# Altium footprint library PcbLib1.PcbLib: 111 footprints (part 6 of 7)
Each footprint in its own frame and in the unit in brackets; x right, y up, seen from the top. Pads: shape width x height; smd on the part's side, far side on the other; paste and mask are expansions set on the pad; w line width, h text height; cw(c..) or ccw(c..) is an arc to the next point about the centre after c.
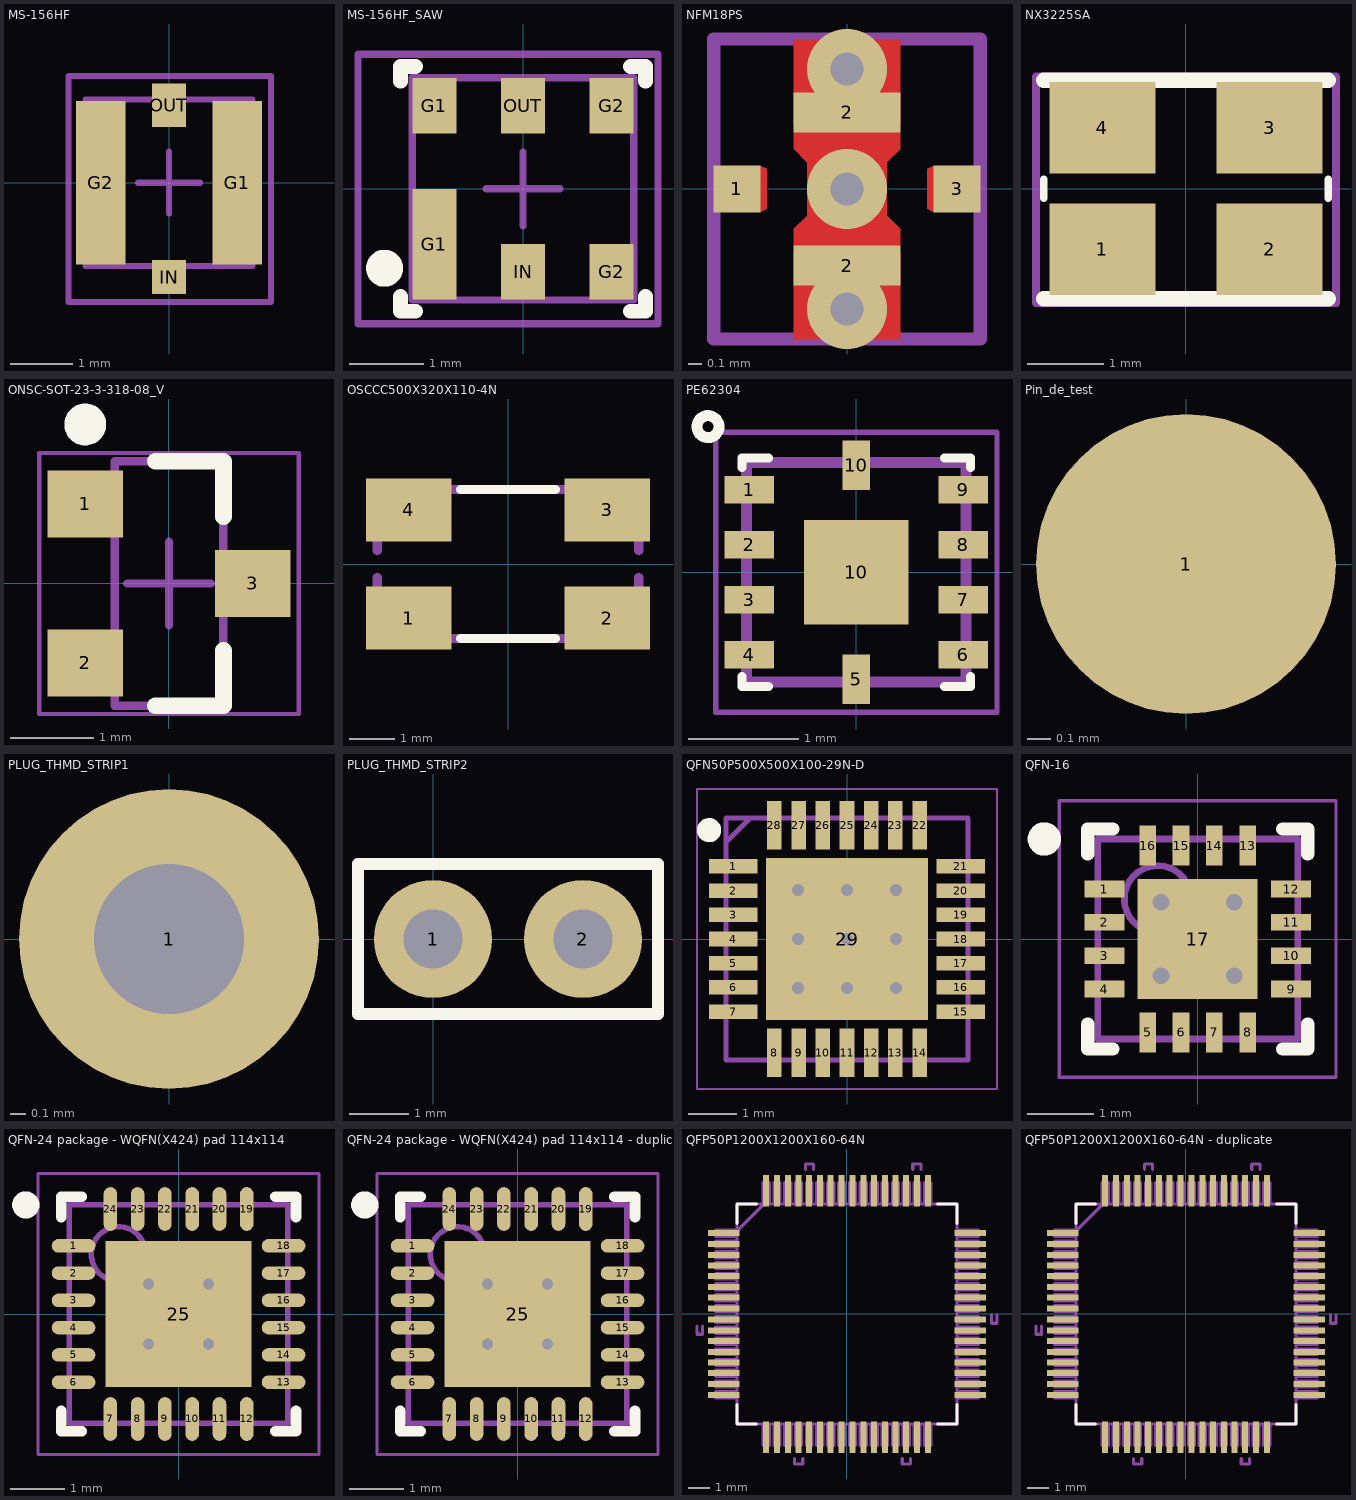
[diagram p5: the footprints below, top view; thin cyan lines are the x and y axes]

## MS-156HF [mm] "Subminiature Coaxial Switch"
height 1.6
pads (4):
  rect 0.8x2.65 smd paste+0 mask+0.051: G1(1.1,0) G2(-1.1,0)
  rect 0.55x0.55 smd paste-0.3 mask+0.051: IN(0,-1.525)
  rect 0.55x0.7 smd paste-0.3 mask+0.051: OUT(0,1.25)
Top Paste:
  rectangle: -0.274,0.9 0.275,1.35
  rectangle: -0.275,-1.55 0.274,-1.251
Top Solder:
  rectangle: -1.551,-1.372 1.551,1.378
Mechanical 13:
  lines w0.1: -1.346,-1.346 -1.346,1.346 1.346,1.346 1.346,-1.346 -1.346,-1.346
Mechanical 15:
  lines w0.1: -0.5,0 0.5,0 ; 0,-0.5 0,0.5 ; -1.626,-1.93 -1.626,1.727 1.651,1.727 1.651,-1.93 -1.626,-1.93
3D body "MS-156HF(ST).STEP": height 1.56, standoff -0.04, extent -1.362,-1.35 1.338,1.35
3D body: height 1.25, standoff 0, extent -1.002,-0.998 0.991,0.998
3D body: height 1, standoff 0, extent -0.3,-0.299 0.298,0.299
3D body: height 1.26, standoff 0.66, extent -0.3,-0.297 0.297,0.3
3D body: height 0.35, standoff 0, extent -1.295,-1.27 1.219,1.27

## MS-156HF_SAW [mm] "Coax swappable with SAW"
height 1
pads (6):
  rect 0.6x1.5 smd paste-0.065 mask+0.1: G1(-1.2,-0.75)
  rect 0.6x0.75 smd paste-0.065 mask+0.1: G1(-1.2,1.125) G2(1.2,-1.125) G2(1.2,1.125) IN(0,-1.125) OUT(0,1.125)
Top Overlay:
  circle w0.25: c-1.875,-1.075 r0.125
  lines w0.2: -1.658,-1.458 -1.658,-1.658 -1.458,-1.658 ; -1.658,1.458 -1.658,1.658 -1.458,1.658 ; 1.458,-1.658 1.658,-1.658 1.658,-1.458 ; 1.458,1.658 1.658,1.658 1.658,1.458
Mechanical 13:
  lines w0.1: -1.499,-1.505 -1.499,1.506 1.499,1.506 1.499,-1.505 -1.499,-1.505
Mechanical 15:
  lines w0.1: -0.5,0 0.5,0 ; 0,-0.5 0,0.5 ; -2.235,-1.829 -2.235,1.825 1.829,1.825 1.829,-1.829 -2.235,-1.829
3D body "MS-156HF(ST).STEP": height 1.56, standoff -0.04, extent -1.35,-1.35 1.35,1.35

## NFM18PS [mm] "Feed Through Capacitor"
height 0.9
pads (4):
  rect 0.35x0.35 smd paste+0 mask+0: 1(-0.825,0) 3(0.825,0)
  rect 0.8x0.3 smd paste+0 mask+0: 2(0,-0.575) 2(0,0.575)
via 0,0 diameter 0.6 hole 0.25
via 0,0.9 diameter 0.6 hole 0.25
via 0,-0.9 diameter 0.6 hole 0.25
Top Layer:
  rectangle: -0.3,-0.2 0.3,0.2
  rectangle: -0.4,0.475 0.4,1.125
  rectangle: -0.4,-1.125 0.4,-0.475
  region: 0.4,-0.425 0.4,-0.3 0.3,-0.2 -0.3,-0.2 -0.4,-0.3 -0.4,-0.425 0,-0.625
  region: -0.4,0.425 -0.4,0.3 -0.3,0.2 0.3,0.2 0.4,0.3 0.4,0.425 0,0.625
  region: 0.65,0.175 0.6,0.15 0.6,-0.15 0.65,-0.175 0.825,0
  region: -0.65,-0.174 -0.6,-0.15 -0.6,0.15 -0.65,0.174 -0.8,0
Top Paste:
  region: -0.65,-0.175 -0.6,-0.15 -0.6,0.15 -0.65,0.175
  region: 0.65,0.175 0.6,0.15 0.6,-0.15 0.65,-0.175
  region: 0.4,-0.425 0.4,-0.3 0.3,-0.2 -0.3,-0.2 -0.4,-0.3 -0.4,-0.425
  region: -0.4,0.425 -0.4,0.3 -0.3,0.2 0.3,0.2 0.4,0.3 0.4,0.425
Top Solder:
  region: -0.65,0.174 -0.6,0.15 -0.6,-0.15 -0.65,-0.174
  region: 0.65,0.175 0.6,0.15 0.6,-0.15 0.65,-0.175
  region: -0.4,0.425 -0.4,0.3 -0.3,0.2 0.3,0.2 0.4,0.3 0.4,0.425
  region: -0.3,-0.2 -0.4,-0.3 -0.4,-0.425 0.4,-0.425 0.4,-0.3 0.3,-0.2
Mechanical 13:
  lines w0.1: -1,-1.125 -1,1.125 1,1.125 1,-1.125 -1,-1.125
3D body: height 0.59, standoff 0, extent -0.8,-0.4 0.8,0.4
3D body: height 0.6, standoff 0, extent -0.4,0.3 0.4,0.427
3D body: height 0.6, standoff 0, extent 0.523,-0.15 0.825,0.15
3D body: height 0.6, standoff 0, extent -0.825,-0.15 -0.523,0.15
3D body: height 0.6, standoff 0, extent -0.4,-0.427 0.4,-0.3

## NX3225SA [mm] "20 MHz Crystal Oscillator"
height 0.7
pads (4):
  rect 1.4x1.2 smd paste+0 mask+0: 1(-1.1,-0.8) 2(1.1,-0.8) 3(1.1,0.8) 4(-1.1,0.8)
Top Overlay:
  lines w0.1: -1.875,-0.129 -1.875,0.125 ; 1.875,-0.129 1.875,0.125
  lines w0.2: -1.875,-1.45 1.875,-1.45 ; -1.875,1.425 1.875,1.425
Mechanical 15:
  lines w0.1: -1.975,-1.512 -1.975,1.475 1.975,1.475 1.975,-1.512 -1.975,-1.512
3D body "User Library-ASTX-H11.STEP": height 1.1, standoff 0, extent -1.65,-1.3 1.65,1.3

## ONSC-SOT-23-3-318-08_V [mm] "SOT23, 3-Leads, Body 2.92x1.3mm, Pitch 0.95mm"
height 1.11
pads (3):
  rect 0.9x0.8 smd: 1(-1,0.95) 2(-1,-0.95) 3(1,0)
Top Overlay:
  circle w0.25: c-1,1.9 r0.125
  lines w0.2: -0.165,-1.46 0.65,-1.46 0.65,-0.8 ; -0.165,1.46 0.65,1.46 0.65,0.8
Mechanical 13:
  lines w0.1: -0.65,-1.46 -0.65,1.46 0.65,1.46 0.65,-1.46 -0.65,-1.46
Mechanical 15:
  lines w0.05: -1.55,-1.56 -1.55,1.56 1.55,1.56 1.55,-1.56 -1.55,-1.56
  lines w0.1: -0.5,0 0.5,0 ; 0,-0.5 0,0.5
3D body: height 1.11, standoff 0.01, extent -0.65,-1.46 0.65,1.46

## OSCCC500X320X110-4N [mm]
pads (4):
  rect 1.9x1.4 smd: 1(-2.2,-1.2) 2(2.2,-1.2) 3(2.2,1.2) 4(-2.2,1.2)
Top Overlay:
  lines w0.203: -1.05,-1.65 1.05,-1.65 ; -1.05,1.65 1.05,1.65
Mechanical 13:
  lines w0.203: -2.902,-1.225 cw(c-2.902,-1.652) -2.475,-1.652 ; -2.902,1.225 ccw(c-2.902,1.652) -2.475,1.652 ; -2.9,-1.225 -2.9,-0.3 ; -2.9,0.3 -2.9,1.225 ; -2.475,-1.65 -1.05,-1.65 ; -2.475,1.65 -1.05,1.65 ; 1.05,-1.65 2.475,-1.65 ; 1.05,1.65 2.475,1.65 ; 2.475,-1.652 cw(c2.902,-1.652) 2.902,-1.225 ; 2.475,1.652 ccw(c2.902,1.652) 2.902,1.225 ; 2.9,-1.225 2.9,-0.3 ; 2.9,0.3 2.9,1.225
3D body "ABM3B-13.000MHZ-10-1-U-T.STEP": height 1.1, standoff 0, extent -2.54,-1.651 2.54,1.651

## PE62304 [mm] "Digitally Tunable Capacitor for GSM/WCDMA"
height 0.95
pads (11):
  rect 0.45x0.25 smd mask+0.05: 1(-0.975,0.75) 2(-0.975,0.25) 3(-0.975,-0.25) 4(-0.975,-0.75) 6(0.975,-0.75) 7(0.975,-0.25) 8(0.975,0.25) 9(0.975,0.75)
  rect 0.25x0.45 smd mask+0.05: 5(0,-0.975) 10(0,0.975)
  rect 0.95x0.95 smd mask+0.05: 10(0,0)
Top Overlay:
  circle w0.1: c-1.35,1.325 r0.1
  lines w0.08: -1.04,-0.95 -1.04,-1.04 -0.8,-1.04 ; -1.04,0.95 -1.04,1.04 -0.8,1.04 ; 0.8,-1.04 1.04,-1.04 1.04,-0.95 ; 0.8,1.04 1.04,1.04 1.04,0.95
Mechanical 13:
  lines w0.1: -1,-1 -1,1 1,1 1,-1 -1,-1
Mechanical 15:
  lines w0.05: -1.28,-1.275 1.28,-1.275 1.28,1.275 -1.28,1.275 -1.28,-1.275
3D body: height 0.6, standoff 0, extent -1,-1.075 1,0.923

## Pin_de_test [mm]
pads (1):
  round 1.27 smd paste-10: 1(0,0)

## PLUG_THMD_STRIP1 [mm]
pads (1):
  round 2 hole 1 paste+0 mask+0: 1(0,0)

## PLUG_THMD_STRIP2 [mm]
pads (2):
  round 2 hole 1 paste+0 mask+0: 1(0,0)
  round 2 / inner round 1.524 / far side round 1.6 hole 1 paste+0 mask+0: 2(2.54,0)
Top Overlay:
  lines w0.203: -1.27,-1.27 -1.27,1.27 3.81,1.27 3.81,-1.27 -1.27,-1.27
Mechanical 13:
  lines w0.203: -1.27,-1.27 3.81,-1.27 3.81,1.27 -1.27,1.27 -1.27,-1.27
  text "1" at -2.156,-0.448 h0.8
3D body "Stripline_1.stp": height 8.57, standoff -2.97, extent -1.27,-1.27 1.27,1.27
3D body "Stripline_1.stp": height 8.57, standoff -2.97, extent 1.27,-1.27 3.81,1.27

## QFN50P500X500X100-29N-D [mm]
pads (29):
  rect 1x0.3 smd: 1(-2.35,1.5) 2(-2.35,1) 3(-2.35,0.5) 4(-2.35,0) 5(-2.35,-0.5) 6(-2.35,-1) 7(-2.35,-1.5) 15(2.35,-1.5) 16(2.35,-1) 17(2.35,-0.5) 18(2.35,0) 19(2.35,0.5) 20(2.35,1) 21(2.35,1.5)
  rect 0.3x1 smd: 8(-1.5,-2.35) 9(-1,-2.35) 10(-0.5,-2.35) 11(0,-2.35) 12(0.5,-2.35) 13(1,-2.35) 14(1.5,-2.35) 22(1.5,2.35) 23(1,2.35) 24(0.5,2.35) 25(0,2.35) 26(-0.5,2.35) 27(-1,2.35) 28(-1.5,2.35)
  rect 3.35x3.35 smd: 29(0,0)
via 0,-1.016 diameter 0.6 hole 0.25
via 0,1.016 diameter 0.6 hole 0.25
via 1.016,-1.016 diameter 0.6 hole 0.25
via 1.016,0 diameter 0.6 hole 0.25
via 1.016,1.016 diameter 0.6 hole 0.25
via 0,0 diameter 0.6 hole 0.25
via -1.016,0 diameter 0.6 hole 0.25
via -1.016,-1.016 diameter 0.6 hole 0.25
via -1.016,1.016 diameter 0.6 hole 0.25
Top Overlay:
  circle w0.25: c-2.85,2.25 r0.125
Mechanical 13:
  lines w0.1: -2.5,2 -2,2.5 ; -2.5,-2.5 -2.5,2.5 2.5,2.5 2.5,-2.5 -2.5,-2.5
Mechanical 15:
  lines w0.05: -3.1,-3.1 -3.1,3.1 3.1,3.1 3.1,-3.1 -3.1,-3.1
3D body "CP2101-GMR.stp": height 1, standoff 0, extent -2.55,-2.55 2.55,2.55

## QFN-16 [mm] "QFN, 16-Leads, Body 3,00x3,00mm, Pitch 0,50mm, Thermal Pad 1,80x1,80mm, IPC Medium Density"
height 0.9
pads (17):
  rect 0.6x0.25 smd: 1(-1.4,0.75) 2(-1.4,0.25) 3(-1.4,-0.25) 4(-1.4,-0.75) 9(1.4,-0.75) 10(1.4,-0.25) 11(1.4,0.25) 12(1.4,0.75)
  rect 0.25x0.6 smd: 5(-0.75,-1.4) 6(-0.25,-1.4) 7(0.25,-1.4) 8(0.75,-1.4) 13(0.75,1.4) 14(0.25,1.4) 15(-0.25,1.4) 16(-0.75,1.4)
  rect 1.8x1.8 smd: 17(0,0)
via -0.55,0.55 diameter 0.6 hole 0.25
via 0.55,0.55 diameter 0.6 hole 0.25
via -0.55,-0.55 diameter 0.6 hole 0.25
via 0.55,-0.55 diameter 0.6 hole 0.25
Top Overlay:
  circle w0.25: c-2.3,1.5 r0.125
  lines w0.2: -1.65,-1.275 -1.65,-1.65 -1.275,-1.65 ; -1.65,1.275 -1.65,1.65 -1.275,1.65 ; 1.275,-1.65 1.65,-1.65 1.65,-1.275 ; 1.275,1.65 1.65,1.65 1.65,1.275
Mechanical 13:
  circle w0.1: c-0.6,0.6 r0.5
  lines w0.1: -1.5,-1.5 -1.5,1.5 1.5,1.5 1.5,-1.5 -1.5,-1.5
Mechanical 15:
  lines w0.05: -2.075,-2.075 -2.075,2.075 2.075,2.075 2.075,-2.075 -2.075,-2.075
  lines w0.1: -0.5,0 0.5,0 ; 0,-0.5 0,0.5
3D body "QFN-16_2.step": height 0.9, standoff 0, extent -1.51,-1.51 1.51,1.51

## QFN-24 package - WQFN(X424) pad 114x114 [mm] "QFN, 24-Leads, Body 4.00x4.00mm, Pitch 0.50mm, Thermal Pad 2.68x2.68mm, IPC Medium Density"
height 0.8
pads (25):
  oval 0.8x0.25 smd: 1(-1.925,1.25) 2(-1.925,0.75) 3(-1.925,0.25) 4(-1.925,-0.25) 5(-1.925,-0.75) 6(-1.925,-1.25) 13(1.925,-1.25) 14(1.925,-0.75) 15(1.925,-0.25) 16(1.925,0.25) 17(1.925,0.75) 18(1.925,1.25)
  oval 0.25x0.8 smd: 7(-1.25,-1.925) 8(-0.75,-1.925) 9(-0.25,-1.925) 10(0.25,-1.925) 11(0.75,-1.925) 12(1.25,-1.925) 19(1.25,1.925) 20(0.75,1.925) 21(0.25,1.925) 22(-0.25,1.925) 23(-0.75,1.925) 24(-1.25,1.925)
  rect 2.68x2.68 smd: 25(0,0)
via 0.55,-0.55 diameter 0.5 hole 0.2
via -0.55,-0.55 diameter 0.5 hole 0.2
via 0.55,0.55 diameter 0.5 hole 0.2
via -0.55,0.55 diameter 0.5 hole 0.2
Top Overlay:
  circle w0.25: c-2.8,2 r0.125
  lines w0.2: -2.15,-1.775 -2.15,-2.15 -1.775,-2.15 ; -2.15,1.775 -2.15,2.15 -1.775,2.15 ; 1.775,-2.15 2.15,-2.15 2.15,-1.775 ; 1.775,2.15 2.15,2.15 2.15,1.775
Mechanical 13:
  circle w0.1: c-1.1,1.1 r0.5
  lines w0.1: -2,-2 2,-2 2,2 -2,2 -2,-2
Mechanical 15:
  lines w0.05: -2.575,-2.575 2.575,-2.575 2.575,2.575 -2.575,2.575 -2.575,-2.575
  lines w0.1: -0.5,0 0.5,0 ; 0,-0.5 0,0.5
3D body: height 0.8, standoff 0, extent -2,-2 2,2

## QFN-24 package - WQFN(X424) pad 114x114 - duplicate [mm] "QFN, 24-Leads, Body 4.00x4.00mm, Pitch 0.50mm, Thermal Pad 2.68x2.68mm, IPC Medium Density"
height 0.8
pads (25):
  oval 0.8x0.25 smd: 1(-1.925,1.25) 2(-1.925,0.75) 3(-1.925,0.25) 4(-1.925,-0.25) 5(-1.925,-0.75) 6(-1.925,-1.25) 13(1.925,-1.25) 14(1.925,-0.75) 15(1.925,-0.25) 16(1.925,0.25) 17(1.925,0.75) 18(1.925,1.25)
  oval 0.25x0.8 smd: 7(-1.25,-1.925) 8(-0.75,-1.925) 9(-0.25,-1.925) 10(0.25,-1.925) 11(0.75,-1.925) 12(1.25,-1.925) 19(1.25,1.925) 20(0.75,1.925) 21(0.25,1.925) 22(-0.25,1.925) 23(-0.75,1.925) 24(-1.25,1.925)
  rect 2.68x2.68 smd: 25(0,0)
via -0.55,0.55 diameter 0.5 hole 0.2
via 0.55,0.55 diameter 0.5 hole 0.2
via -0.55,-0.55 diameter 0.5 hole 0.2
via 0.55,-0.55 diameter 0.5 hole 0.2
Top Overlay:
  circle w0.25: c-2.8,2 r0.125
  lines w0.2: -2.15,-1.775 -2.15,-2.15 -1.775,-2.15 ; -2.15,1.775 -2.15,2.15 -1.775,2.15 ; 1.775,-2.15 2.15,-2.15 2.15,-1.775 ; 1.775,2.15 2.15,2.15 2.15,1.775
Mechanical 13:
  circle w0.1: c-1.1,1.1 r0.5
  lines w0.1: -2,-2 -2,2 2,2 2,-2 -2,-2
Mechanical 15:
  lines w0.05: -2.575,-2.575 -2.575,2.575 2.575,2.575 2.575,-2.575 -2.575,-2.575
  lines w0.1: -0.5,0 0.5,0 ; 0,-0.5 0,0.5
3D body: height 0.8, standoff 0, extent -2,-2 2,2

## QFP50P1200X1200X160-64N [mil]
pads (64):
  rect 58x11 smd: 1(-225,148) 2(-225,128) 3(-225,108) 4(-225,89) 5(-225,69) 6(-225,49) 7(-225,30) 8(-225,10) 9(-225,-10) 10(-225,-30) 11(-225,-49) 12(-225,-69) 13(-225,-89) 14(-225,-108) 15(-225,-128) 16(-225,-148) 33(225,-148) 34(225,-128) 35(225,-108) 36(225,-89) 37(225,-69) 38(225,-49) 39(225,-30) 40(225,-10) 41(225,10) 42(225,30) 43(225,49) 44(225,69) 45(225,89) 46(225,108) 47(225,128) 48(225,148)
  rect 11x58 smd: 17(-148,-225) 18(-128,-225) 19(-108,-225) 20(-89,-225) 21(-69,-225) 22(-49,-225) 23(-30,-225) 24(-10,-225) 25(10,-225) 26(30,-225) 27(49,-225) 28(69,-225) 29(89,-225) 30(108,-225) 31(128,-225) 32(148,-225) 49(148,225) 50(128,225) 51(108,225) 52(89,225) 53(69,225) 54(49,225) 55(30,225) 56(10,225) 57(-10,225) 58(-30,225) 59(-49,225) 60(-69,225) 61(-89,225) 62(-108,225) 63(-128,225) 64(-148,225)
Top Overlay:
  lines w6: -201,-166 -201,-201 -166,-201 ; -201,166 -201,201 -166,201 ; 166,-201 201,-201 201,-166 ; 166,201 201,201 201,166
Mechanical 13:
  drawing of 281 lines, arcs and shapes, not listed
  text "*" at -1614.86,786.08 h267.39
3D body "step_temp.STEP": height 62.99, standoff 0, extent -236.57,-236.57 236.57,236.57

## QFP50P1200X1200X160-64N - duplicate [mil]
pads (64):
  rect 58x11 smd: 1(-225,148) 2(-225,128) 3(-225,108) 4(-225,89) 5(-225,69) 6(-225,49) 7(-225,30) 8(-225,10) 9(-225,-10) 10(-225,-30) 11(-225,-49) 12(-225,-69) 13(-225,-89) 14(-225,-108) 15(-225,-128) 16(-225,-148) 33(225,-148) 34(225,-128) 35(225,-108) 36(225,-89) 37(225,-69) 38(225,-49) 39(225,-30) 40(225,-10) 41(225,10) 42(225,30) 43(225,49) 44(225,69) 45(225,89) 46(225,108) 47(225,128) 48(225,148)
  rect 11x58 smd: 17(-148,-225) 18(-128,-225) 19(-108,-225) 20(-89,-225) 21(-69,-225) 22(-49,-225) 23(-30,-225) 24(-10,-225) 25(10,-225) 26(30,-225) 27(49,-225) 28(69,-225) 29(89,-225) 30(108,-225) 31(128,-225) 32(148,-225) 49(148,225) 50(128,225) 51(108,225) 52(89,225) 53(69,225) 54(49,225) 55(30,225) 56(10,225) 57(-10,225) 58(-30,225) 59(-49,225) 60(-69,225) 61(-89,225) 62(-108,225) 63(-128,225) 64(-148,225)
Top Overlay:
  lines w6: -201,-166 -201,-201 -166,-201 ; -201,166 -201,201 -166,201 ; 166,-201 201,-201 201,-166 ; 166,201 201,201 201,166
Mechanical 13:
  drawing of 281 lines, arcs and shapes, not listed
  text "*" at -1614.86,786.08 h267.39
3D body "step_temp.STEP": height 62.99, standoff 0, extent -236.57,-236.57 236.57,236.57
